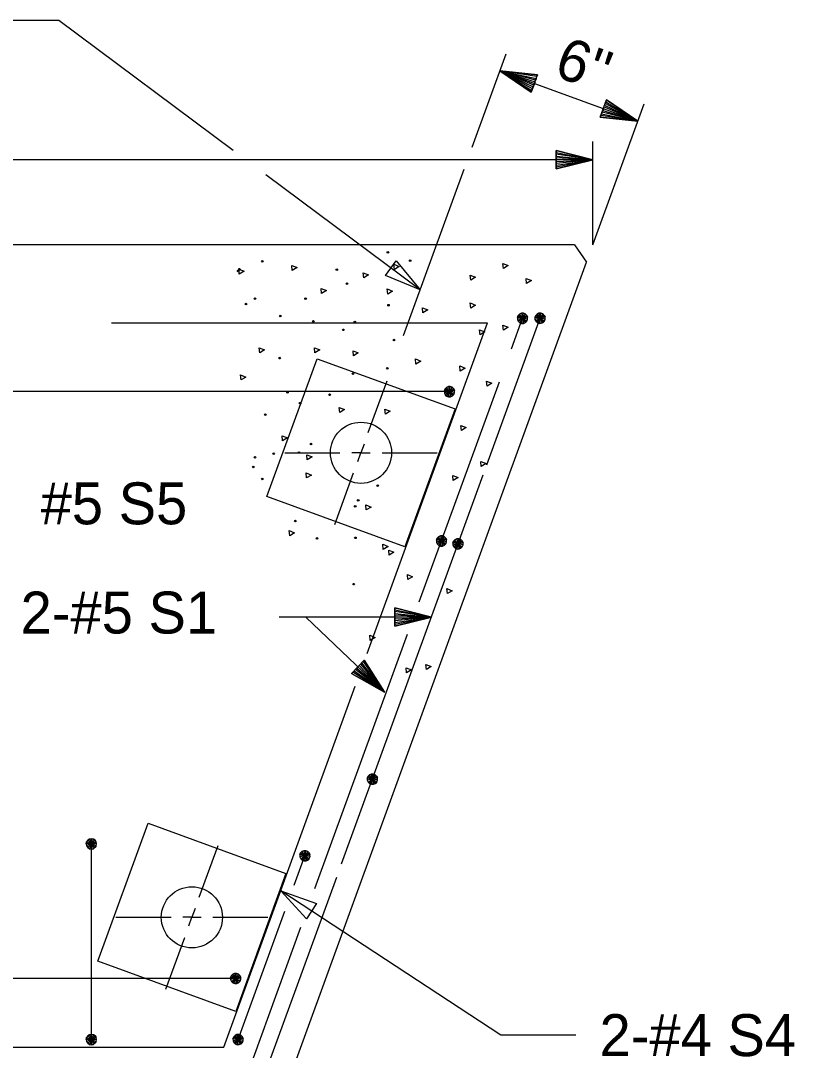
# Model space of a CAD drawing. Extents: x -408 to -23, y -15 to 117.
# Drawn here: x -73.415 to -70.778, y 60.38 to 63.89 of the extents above; entities that cross this region are included whole.
import ezdxf

# ---------------------------------------------------------------- set-up
doc = ezdxf.new("R2010")
doc.units = 0
for name, color, linetype in [('Arrowhead Terminators CELL', 7, 'Continuous'), ('Dimension Lines', 7, 'Continuous'), ('Rebar Lines', 7, 'Continuous'), ('Sup Concrete Girder Lines', 7, 'Continuous'), ('Sup Cored Slab Unit', 7, 'Continuous'), ('Text', 7, 'Continuous')]:
    doc.layers.add(name, color=color, linetype=linetype)

msp = doc.modelspace()

# ---------------------------------------------------------------- linework, layer by layer
at = {"layer": 'Arrowhead Terminators CELL'}
for points in [[(-72.0531, 62.9716), (-72.172, 63.0213), (-72.1347, 63.0714)], [(-72.5287, 60.9234), (-72.407, 60.881), (-72.4413, 60.8288)]]:
    msp.add_lwpolyline(points, close=True, dxfattribs=at)
at = {"layer": 'Dimension Lines'}
for p, q in [((-71.8758, 63.4587), (-71.7601, 63.7768)), ((-71.7814, 63.7181), (-71.3116, 63.5471)), ((-71.4651, 63.1251), (-71.2902, 63.6058)), ((-71.4651, 63.1251), (-71.4651, 63.4781)), ((-71.4651, 63.4156), (-75.257, 63.4156)), ((-72.1097, 62.8161), (-71.9032, 63.3835)), ((-72.2302, 62.4855), (-72.166, 62.6616)), ((-72.5142, 62.4168), (-72.3267, 62.4168)), ((-72.1835, 62.4169), (-71.996, 62.4168)), ((-72.3442, 62.172), (-72.2801, 62.3482)), ((-72.0153, 61.8567), (-72.4433, 61.8568)), ((-72.8062, 60.9023), (-72.742, 61.0785)), ((-73.0903, 60.8337), (-72.9027, 60.8337)), ((-72.7596, 60.8337), (-72.5721, 60.8337)), ((-72.9203, 60.5889), (-72.8561, 60.765))]:
    msp.add_line(p, q, dxfattribs=at)
for points in [[(-72.6909, 63.4471), (-73.285, 63.8898), (-73.8439, 63.8898)], [(-71.664, 63.6753), (-71.6661, 63.6694), (-71.7814, 63.7181), (-71.6683, 63.6636), (-71.6704, 63.6577), (-71.7814, 63.7181), (-71.6725, 63.6518), (-71.6747, 63.6459), (-71.7814, 63.7181), (-71.6533, 63.7047), (-71.6555, 63.6988), (-71.7814, 63.7181), (-71.6576, 63.693), (-71.6597, 63.6871), (-71.7814, 63.7181), (-71.6619, 63.6812), (-71.6747, 63.6459), (-71.6533, 63.7047), (-71.7814, 63.7181), (-71.6747, 63.6459)], [(-71.429, 63.5898), (-71.4311, 63.5839), (-71.3116, 63.5471), (-71.4333, 63.5781), (-71.4355, 63.5722), (-71.3116, 63.5471), (-71.4376, 63.5663), (-71.4397, 63.5605), (-71.3116, 63.5471), (-71.4183, 63.6192), (-71.4205, 63.6133), (-71.3116, 63.5471), (-71.4226, 63.6075), (-71.4248, 63.6015), (-71.3116, 63.5471), (-71.4269, 63.5957), (-71.4397, 63.5605), (-71.4183, 63.6192), (-71.3116, 63.5471), (-71.4397, 63.5605)], [(-71.5901, 63.4156), (-71.5901, 63.4094), (-71.4651, 63.4156), (-71.5901, 63.4031), (-71.5901, 63.3969), (-71.4651, 63.4156), (-71.5901, 63.3906), (-71.5901, 63.3844), (-71.4651, 63.4156), (-71.5901, 63.4469), (-71.5901, 63.4406), (-71.4651, 63.4156), (-71.5901, 63.4344), (-71.5901, 63.4281), (-71.4651, 63.4156), (-71.5901, 63.4219), (-71.5901, 63.3844), (-71.5901, 63.4469), (-71.4651, 63.4156), (-71.5901, 63.3844)], [(-72.0531, 62.9716), (-72.5796, 63.364)], [(-72.2443, 62.4462), (-72.2551, 62.4168), (-72.2235, 62.4167)], [(-72.2661, 62.3871), (-72.2554, 62.4166), (-72.2868, 62.4166)], [(-72.1403, 61.8567), (-72.1403, 61.8505), (-72.0153, 61.8567), (-72.1403, 61.8442), (-72.1403, 61.838), (-72.0153, 61.8567), (-72.1403, 61.8317), (-72.1403, 61.8255), (-72.0153, 61.8567), (-72.1403, 61.888), (-72.1403, 61.8817), (-72.0153, 61.8567), (-72.1403, 61.8755), (-72.1403, 61.8692), (-72.0153, 61.8567), (-72.1403, 61.863), (-72.1403, 61.8255), (-72.1403, 61.888), (-72.0153, 61.8567), (-72.1403, 61.8255)], [(-72.1749, 61.6013), (-72.4433, 61.8568), (-72.5342, 61.8568)], [(-72.2655, 61.6875), (-72.2697, 61.683), (-72.1749, 61.6013), (-72.274, 61.6784), (-72.2784, 61.6739), (-72.1749, 61.6013), (-72.2827, 61.6694), (-72.287, 61.6649), (-72.1749, 61.6013), (-72.2439, 61.7101), (-72.2482, 61.7056), (-72.1749, 61.6013), (-72.2525, 61.7011), (-72.2568, 61.6965), (-72.1749, 61.6013), (-72.2611, 61.692), (-72.287, 61.6649), (-72.2439, 61.7101), (-72.1749, 61.6013), (-72.287, 61.6649)], [(-71.5229, 60.4319), (-71.7788, 60.4319), (-72.5287, 60.9234)], [(-72.8203, 60.8631), (-72.8312, 60.8337), (-72.7996, 60.8336)], [(-72.8421, 60.804), (-72.8315, 60.8335), (-72.8629, 60.8335)]]:
    msp.add_lwpolyline(points, dxfattribs=at)
at = {"layer": 'Rebar Lines'}
for p, q in [((-71.8266, 62.3756), (-71.6448, 62.8751)), ((-71.7425, 62.7708), (-71.7045, 62.8751)), ((-73.1061, 62.8595), (-71.824, 62.8595)), ((-72.2343, 61.7322), (-71.824, 62.8595)), ((-72.0564, 61.9085), (-71.7834, 62.6584)), ((-71.9536, 62.6251), (-74.6002, 62.6251)), ((-72.0185, 61.8483), (-71.8389, 62.3417)), ((-72.3213, 61.0161), (-72.0184, 61.8483)), ((-72.412, 60.9313), (-72.0963, 61.7987)), ((-72.7226, 60.3908), (-72.2748, 61.6211)), ((-73.1742, 60.4168), (-73.1742, 61.0834)), ((-72.4825, 60.9434), (-72.4462, 61.0433)), ((-72.5622, 60.3543), (-72.338, 60.9704)), ((-72.6742, 60.4168), (-72.5147, 60.8549)), ((-72.622, 60.3543), (-72.46, 60.7994)), ((-72.6822, 60.6251), (-75.3697, 60.6251)), ((-74.0047, 60.3908), (-72.7226, 60.3908))]:
    msp.add_line(p, q, dxfattribs=at)
for points in [[(-71.6872, 62.8721), (-71.6873, 62.8789), (-71.69, 62.8852), (-71.695, 62.89), (-71.7015, 62.8925), (-71.7083, 62.8923), (-71.7146, 62.8896), (-71.7194, 62.8846), (-71.7219, 62.8782), (-71.7217, 62.8713), (-71.7189, 62.865), (-71.714, 62.8602), (-71.7076, 62.8577), (-71.7007, 62.8579), (-71.6945, 62.8607), (-71.6897, 62.8656), (-71.6872, 62.8721), (-71.7045, 62.8751), (-71.7219, 62.8782), (-71.7194, 62.8846), (-71.7045, 62.8751), (-71.7146, 62.8896), (-71.7083, 62.8923), (-71.7045, 62.8751), (-71.7015, 62.8925), (-71.695, 62.89), (-71.7045, 62.8751), (-71.69, 62.8852), (-71.6873, 62.8789), (-71.7045, 62.8751), (-71.6897, 62.8656), (-71.6945, 62.8607), (-71.7045, 62.8751), (-71.7007, 62.8579), (-71.7076, 62.8577), (-71.7045, 62.8751), (-71.714, 62.8602), (-71.7189, 62.865), (-71.7045, 62.8751), (-71.7217, 62.8713)], [(-71.6274, 62.8721), (-71.6275, 62.8789), (-71.6303, 62.8852), (-71.6353, 62.89), (-71.6417, 62.8925), (-71.6486, 62.8924), (-71.6549, 62.8896), (-71.6596, 62.8847), (-71.6621, 62.8782), (-71.662, 62.8714), (-71.6592, 62.8651), (-71.6543, 62.8603), (-71.6478, 62.8578), (-71.6409, 62.858), (-71.6347, 62.8607), (-71.6299, 62.8657), (-71.6274, 62.8721), (-71.6448, 62.8751), (-71.6621, 62.8782), (-71.6596, 62.8847), (-71.6448, 62.8751), (-71.6549, 62.8896), (-71.6486, 62.8924), (-71.6448, 62.8751), (-71.6417, 62.8925), (-71.6353, 62.89), (-71.6448, 62.8751), (-71.6303, 62.8852), (-71.6275, 62.8789), (-71.6448, 62.8751), (-71.6299, 62.8657), (-71.6347, 62.8607), (-71.6448, 62.8751), (-71.6409, 62.858), (-71.6478, 62.8578), (-71.6448, 62.8751), (-71.6543, 62.8603), (-71.6592, 62.8651), (-71.6448, 62.8751), (-71.662, 62.8714)], [(-71.9363, 62.6221), (-71.9364, 62.6289), (-71.9391, 62.6352), (-71.9441, 62.64), (-71.9506, 62.6425), (-71.9574, 62.6424), (-71.9637, 62.6396), (-71.9684, 62.6346), (-71.9709, 62.6282), (-71.9708, 62.6213), (-71.968, 62.615), (-71.9631, 62.6102), (-71.9566, 62.6077), (-71.9498, 62.6079), (-71.9435, 62.6107), (-71.9387, 62.6157), (-71.9363, 62.6221), (-71.9536, 62.6251), (-71.9709, 62.6282), (-71.9684, 62.6346), (-71.9536, 62.6251), (-71.9637, 62.6396), (-71.9574, 62.6424), (-71.9536, 62.6251), (-71.9506, 62.6425), (-71.9441, 62.64), (-71.9536, 62.6251), (-71.9391, 62.6352), (-71.9364, 62.6289), (-71.9536, 62.6251), (-71.9387, 62.6157), (-71.9435, 62.6107), (-71.9536, 62.6251), (-71.9498, 62.6079), (-71.9566, 62.6077), (-71.9536, 62.6251), (-71.9631, 62.6102), (-71.968, 62.615), (-71.9536, 62.6251), (-71.9708, 62.6213)], [(-71.9635, 62.113), (-71.9636, 62.1198), (-71.9663, 62.1261), (-71.9713, 62.1309), (-71.9777, 62.1334), (-71.9846, 62.1333), (-71.9909, 62.1305), (-71.9956, 62.1256), (-71.9982, 62.1191), (-71.998, 62.1123), (-71.9952, 62.106), (-71.9903, 62.1012), (-71.9839, 62.0987), (-71.977, 62.0988), (-71.9707, 62.1016), (-71.9659, 62.1065), (-71.9635, 62.113), (-71.9808, 62.1161), (-71.9982, 62.1191), (-71.9956, 62.1256), (-71.9808, 62.1161), (-71.9909, 62.1305), (-71.9846, 62.1333), (-71.9808, 62.1161), (-71.9777, 62.1334), (-71.9713, 62.1309), (-71.9808, 62.1161), (-71.9663, 62.1261), (-71.9636, 62.1198), (-71.9808, 62.1161), (-71.9659, 62.1065), (-71.9707, 62.1016), (-71.9808, 62.1161), (-71.977, 62.0988), (-71.9839, 62.0987), (-71.9808, 62.1161), (-71.9903, 62.1012), (-71.9952, 62.106), (-71.9808, 62.1161), (-71.998, 62.1123)], [(-71.9073, 62.1031), (-71.9074, 62.1099), (-71.9102, 62.1162), (-71.9151, 62.121), (-71.9216, 62.1235), (-71.9284, 62.1234), (-71.9347, 62.1206), (-71.9395, 62.1157), (-71.942, 62.1092), (-71.9418, 62.1024), (-71.939, 62.0961), (-71.9342, 62.0913), (-71.9277, 62.0888), (-71.9208, 62.0889), (-71.9146, 62.0917), (-71.9098, 62.0966), (-71.9073, 62.1031), (-71.9246, 62.1061), (-71.942, 62.1092), (-71.9395, 62.1157), (-71.9246, 62.1061), (-71.9347, 62.1206), (-71.9284, 62.1234), (-71.9246, 62.1061), (-71.9216, 62.1235), (-71.9151, 62.121), (-71.9246, 62.1061), (-71.9102, 62.1162), (-71.9074, 62.1099), (-71.9246, 62.1061), (-71.9098, 62.0966), (-71.9146, 62.0917), (-71.9246, 62.1061), (-71.9208, 62.0889), (-71.9277, 62.0888), (-71.9246, 62.1061), (-71.9342, 62.0913), (-71.939, 62.0961), (-71.9246, 62.1061), (-71.9418, 62.1024)], [(-72.199, 61.3015), (-72.1991, 61.3084), (-72.2019, 61.3147), (-72.2069, 61.3195), (-72.2133, 61.3219), (-72.2201, 61.3218), (-72.2264, 61.319), (-72.2312, 61.314), (-72.2337, 61.3076), (-72.2335, 61.3008), (-72.2308, 61.2945), (-72.2258, 61.2897), (-72.2194, 61.2872), (-72.2125, 61.2873), (-72.2062, 61.2901), (-72.2014, 61.2951), (-72.199, 61.3015), (-72.2163, 61.3046), (-72.2337, 61.3076), (-72.2312, 61.314), (-72.2163, 61.3046), (-72.2264, 61.319), (-72.2201, 61.3218), (-72.2163, 61.3046), (-72.2133, 61.3219), (-72.2069, 61.3195), (-72.2163, 61.3046), (-72.2019, 61.3147), (-72.1991, 61.3084), (-72.2163, 61.3046), (-72.2014, 61.2951), (-72.2062, 61.2901), (-72.2163, 61.3046), (-72.2125, 61.2873), (-72.2194, 61.2872), (-72.2163, 61.3046), (-72.2258, 61.2897), (-72.2308, 61.2945), (-72.2163, 61.3046), (-72.2335, 61.3008)], [(-73.1566, 61.0834), (-73.1579, 61.0901), (-73.1617, 61.0959), (-73.1674, 61.0997), (-73.1742, 61.101), (-73.1809, 61.0997), (-73.1867, 61.0959), (-73.1905, 61.0902), (-73.1918, 61.0834), (-73.1905, 61.0767), (-73.1867, 61.071), (-73.181, 61.0671), (-73.1742, 61.0658), (-73.1674, 61.0671), (-73.1618, 61.0709), (-73.1579, 61.0766), (-73.1566, 61.0834), (-73.1742, 61.0834), (-73.1918, 61.0834), (-73.1905, 61.0902), (-73.1742, 61.0834), (-73.1867, 61.0959), (-73.1809, 61.0997), (-73.1742, 61.0834), (-73.1742, 61.101), (-73.1674, 61.0997), (-73.1742, 61.0834), (-73.1617, 61.0959), (-73.1579, 61.0901), (-73.1742, 61.0834), (-73.1579, 61.0766), (-73.1618, 61.0709), (-73.1742, 61.0834), (-73.1674, 61.0671), (-73.1742, 61.0658), (-73.1742, 61.0834), (-73.181, 61.0671), (-73.1867, 61.071), (-73.1742, 61.0834), (-73.1905, 61.0767)], [(-72.4289, 61.0402), (-72.429, 61.047), (-72.4317, 61.0533), (-72.4367, 61.0581), (-72.4431, 61.0605), (-72.45, 61.0604), (-72.4563, 61.0576), (-72.461, 61.0527), (-72.4635, 61.0463), (-72.4634, 61.0394), (-72.4606, 61.0331), (-72.4557, 61.0283), (-72.4493, 61.0258), (-72.4423, 61.026), (-72.4361, 61.0288), (-72.4313, 61.0337), (-72.4289, 61.0402), (-72.4462, 61.0432), (-72.4635, 61.0463), (-72.461, 61.0527), (-72.4462, 61.0432), (-72.4563, 61.0576), (-72.45, 61.0604), (-72.4462, 61.0432), (-72.4431, 61.0605), (-72.4367, 61.0581), (-72.4462, 61.0432), (-72.4317, 61.0533), (-72.429, 61.047), (-72.4462, 61.0432), (-72.4313, 61.0337), (-72.4361, 61.0288), (-72.4462, 61.0432), (-72.4423, 61.026), (-72.4493, 61.0258), (-72.4462, 61.0432), (-72.4557, 61.0283), (-72.4606, 61.0331), (-72.4462, 61.0432), (-72.4634, 61.0394)], [(-72.6649, 60.6221), (-72.665, 60.6289), (-72.6678, 60.6352), (-72.6727, 60.64), (-72.6792, 60.6425), (-72.686, 60.6424), (-72.6923, 60.6396), (-72.697, 60.6346), (-72.6995, 60.6282), (-72.6994, 60.6213), (-72.6966, 60.615), (-72.6917, 60.6102), (-72.6853, 60.6077), (-72.6784, 60.6079), (-72.6721, 60.6107), (-72.6673, 60.6157), (-72.6649, 60.6221), (-72.6822, 60.6251), (-72.6995, 60.6282), (-72.697, 60.6346), (-72.6822, 60.6251), (-72.6923, 60.6396), (-72.686, 60.6424), (-72.6822, 60.6251), (-72.6792, 60.6425), (-72.6727, 60.64), (-72.6822, 60.6251), (-72.6678, 60.6352), (-72.665, 60.6289), (-72.6822, 60.6251), (-72.6673, 60.6157), (-72.6721, 60.6107), (-72.6822, 60.6251), (-72.6784, 60.6079), (-72.6853, 60.6077), (-72.6822, 60.6251), (-72.6917, 60.6102), (-72.6966, 60.615), (-72.6822, 60.6251), (-72.6994, 60.6213)], [(-73.1566, 60.4168), (-73.1579, 60.4235), (-73.1617, 60.4292), (-73.1674, 60.4331), (-73.1742, 60.4344), (-73.1809, 60.4331), (-73.1867, 60.4292), (-73.1905, 60.4235), (-73.1918, 60.4168), (-73.1905, 60.41), (-73.1867, 60.4043), (-73.181, 60.4005), (-73.1742, 60.3991), (-73.1674, 60.4005), (-73.1618, 60.4043), (-73.1579, 60.41), (-73.1566, 60.4168), (-73.1742, 60.4168), (-73.1918, 60.4168), (-73.1905, 60.4235), (-73.1742, 60.4168), (-73.1867, 60.4292), (-73.1809, 60.4331), (-73.1742, 60.4168), (-73.1742, 60.4344), (-73.1674, 60.4331), (-73.1742, 60.4168), (-73.1617, 60.4292), (-73.1579, 60.4235), (-73.1742, 60.4168), (-73.1579, 60.41), (-73.1618, 60.4043), (-73.1742, 60.4168), (-73.1674, 60.4005), (-73.1742, 60.3991), (-73.1742, 60.4168), (-73.181, 60.4005), (-73.1867, 60.4043), (-73.1742, 60.4168), (-73.1905, 60.41)], [(-72.6569, 60.4137), (-72.657, 60.4206), (-72.6597, 60.4269), (-72.6647, 60.4316), (-72.6711, 60.4341), (-72.678, 60.434), (-72.6843, 60.4312), (-72.689, 60.4262), (-72.6915, 60.4198), (-72.6913, 60.413), (-72.6886, 60.4066), (-72.6837, 60.4019), (-72.6773, 60.3994), (-72.6703, 60.3995), (-72.6641, 60.4023), (-72.6593, 60.4073), (-72.6569, 60.4137), (-72.6742, 60.4168), (-72.6915, 60.4198), (-72.689, 60.4262), (-72.6742, 60.4168), (-72.6843, 60.4312), (-72.678, 60.434), (-72.6742, 60.4168), (-72.6711, 60.4341), (-72.6647, 60.4316), (-72.6742, 60.4168), (-72.6597, 60.4269), (-72.657, 60.4206), (-72.6742, 60.4168), (-72.6593, 60.4073), (-72.6641, 60.4023), (-72.6742, 60.4168), (-72.6703, 60.3995), (-72.6773, 60.3994), (-72.6742, 60.4168), (-72.6837, 60.4019), (-72.6886, 60.4066), (-72.6742, 60.4168), (-72.6913, 60.413)]]:
    msp.add_lwpolyline(points, dxfattribs=at)
at = {"layer": 'Sup Concrete Girder Lines'}
for p, q in [((-71.5276, 63.1251), (-77.0833, 63.1251)), ((-71.5276, 63.1251), (-71.4864, 63.0664)), ((-72.557, 60.1251), (-71.4864, 63.0664))]:
    msp.add_line(p, q, dxfattribs=at)
for points in [[(-72.67, 63.0255), (-72.6715, 63.0427), (-72.6535, 63.0356), (-72.67, 63.0255)], [(-72.4897, 63.0378), (-72.4912, 63.055), (-72.4732, 63.0479), (-72.4897, 63.0378)], [(-72.1414, 63.0419), (-72.1428, 63.0591), (-72.1249, 63.052), (-72.1414, 63.0419)], [(-71.7699, 63.0451), (-71.7713, 63.0623), (-71.7534, 63.0552), (-71.7699, 63.0451)], [(-72.2459, 63.0132), (-72.2473, 63.0304), (-72.2294, 63.0233), (-72.2459, 63.0132)], [(-71.8811, 63.0053), (-71.8826, 63.0226), (-71.8646, 63.0155), (-71.8811, 63.0053)], [(-71.6904, 62.9935), (-71.6919, 63.0107), (-71.6739, 63.0036), (-71.6904, 62.9935)], [(-72.3893, 62.9599), (-72.3908, 62.9772), (-72.3728, 62.97), (-72.3893, 62.9599)], [(-72.1639, 62.9578), (-72.1654, 62.9751), (-72.1474, 62.968), (-72.1639, 62.9578)], [(-72.044, 62.8941), (-72.0455, 62.9113), (-72.0275, 62.9042), (-72.044, 62.8941)], [(-71.8811, 62.91), (-71.8826, 62.9273), (-71.8646, 62.9201), (-71.8811, 62.91)], [(-71.8494, 62.8186), (-71.8508, 62.8359), (-71.8328, 62.8287), (-71.8494, 62.8186)], [(-71.7699, 62.8345), (-71.7713, 62.8518), (-71.7534, 62.8446), (-71.7699, 62.8345)], [(-72.6003, 62.7571), (-72.6018, 62.7743), (-72.5838, 62.7672), (-72.6003, 62.7571)], [(-72.4119, 62.7571), (-72.4133, 62.7743), (-72.3953, 62.7672), (-72.4119, 62.7571)], [(-72.2807, 62.7468), (-72.2822, 62.764), (-72.2642, 62.7569), (-72.2807, 62.7468)], [(-72.0678, 62.7193), (-72.0693, 62.7365), (-72.0513, 62.7294), (-72.0678, 62.7193)], [(-71.9169, 62.6955), (-71.9184, 62.7127), (-71.9004, 62.7056), (-71.9169, 62.6955)], [(-72.6639, 62.6649), (-72.6653, 62.6821), (-72.6474, 62.675), (-72.6639, 62.6649)], [(-71.8255, 62.6438), (-71.827, 62.6611), (-71.809, 62.6539), (-71.8255, 62.6438)], [(-72.3278, 62.5542), (-72.3293, 62.5714), (-72.3113, 62.5643), (-72.3278, 62.5542)], [(-72.1721, 62.5481), (-72.1736, 62.5653), (-72.1556, 62.5582), (-72.1721, 62.5481)], [(-71.9129, 62.4928), (-71.9144, 62.5101), (-71.8964, 62.503), (-71.9129, 62.4928)], [(-72.5225, 62.4579), (-72.5239, 62.4751), (-72.506, 62.468), (-72.5225, 62.4579)], [(-72.4385, 62.3923), (-72.4399, 62.4096), (-72.422, 62.4024), (-72.4385, 62.3923)], [(-71.8453, 62.3697), (-71.8468, 62.3869), (-71.8288, 62.3798), (-71.8453, 62.3697)], [(-72.4406, 62.3309), (-72.442, 62.3481), (-72.424, 62.341), (-72.4406, 62.3309)], [(-71.9407, 62.322), (-71.9422, 62.3393), (-71.9242, 62.3321), (-71.9407, 62.322)], [(-72.2373, 62.2218), (-72.2387, 62.2391), (-72.2208, 62.2319), (-72.2373, 62.2218)], [(-72.4979, 62.1342), (-72.4994, 62.1514), (-72.4814, 62.1443), (-72.4979, 62.1342)], [(-72.1791, 62.0876), (-72.1806, 62.1048), (-72.1626, 62.0977), (-72.1791, 62.0876)], [(-72.1593, 62.0677), (-72.1607, 62.0849), (-72.1427, 62.0778), (-72.1593, 62.0677)], [(-72.0957, 61.9843), (-72.0971, 62.0015), (-72.0792, 61.9944), (-72.0957, 61.9843)], [(-71.9606, 61.9366), (-71.9621, 61.9538), (-71.9441, 61.9467), (-71.9606, 61.9366)], [(-72.2235, 61.7775), (-72.225, 61.7948), (-72.207, 61.7876), (-72.2235, 61.7775)], [(-72.0997, 61.6664), (-72.1011, 61.6837), (-72.0832, 61.6765), (-72.0997, 61.6664)], [(-72.0321, 61.6784), (-72.0336, 61.6956), (-72.0156, 61.6885), (-72.0321, 61.6784)]]:
    msp.add_lwpolyline(points, dxfattribs=at)
for centre, radius in [((-72.1634, 63.1), 0.00273), ((-72.0876, 63.0714), 0.00273), ((-72.6736, 63.0365), 0.00273), ((-72.6695, 63.0427), 0.00273), ((-72.5916, 63.0693), 0.00273), ((-72.3375, 63.0406), 0.00273), ((-72.3027, 62.9935), 0.00273), ((-72.6162, 62.9423), 0.00273), ((-72.4441, 62.9423), 0.00273), ((-72.647, 62.9238), 0.00273), ((-72.1613, 62.9197), 0.00273), ((-72.5301, 62.8828), 0.00273), ((-72.4174, 62.8644), 0.00273), ((-72.2761, 62.8624), 0.00273), ((-72.315, 62.8358), 0.00273), ((-72.1429, 62.8009), 0.00273), ((-72.5322, 62.7394), 0.00273), ((-72.2822, 62.6862), 0.00273), ((-72.1655, 62.7046), 0.00273), ((-72.5056, 62.6226), 0.00273), ((-72.4625, 62.5858), 0.00273), ((-72.3621, 62.6144), 0.00273), ((-72.5814, 62.5468), 0.00273), ((-72.2551, 62.4168), 0.1042), ((-72.4257, 62.4464), 0.00273), ((-72.5527, 62.4136), 0.00273), ((-72.4667, 62.4177), 0.00273), ((-72.6162, 62.4013), 0.00273), ((-72.6223, 62.3686), 0.00273), ((-72.5916, 62.3276), 0.00273), ((-72.1982, 62.305), 0.00273), ((-72.2748, 62.234), 0.00273), ((-72.2646, 62.2545), 0.00273), ((-72.4789, 62.1841), 0.00273), ((-72.4051, 62.1248), 0.00273), ((-72.274, 62.1268), 0.00273), ((-72.2802, 61.969), 0.00273), ((-72.8315, 60.8335), 0.1042)]:
    msp.add_circle(centre, radius, dxfattribs=at)
at = {"layer": 'Sup Cored Slab Unit'}
for points in [[(-72.4045, 62.7372), (-71.9346, 62.5662), (-72.1056, 62.0964), (-72.5755, 62.2674)], [(-72.9809, 61.1539), (-72.511, 60.9829), (-72.6821, 60.513), (-73.1519, 60.6841)]]:
    msp.add_lwpolyline(points, close=True, dxfattribs=at)

# ---------------------------------------------------------------- texts
at = {"layer": 'Text'}
msp.add_text("6''", height=0.14302, rotation=340.0105, dxfattribs=at).set_placement((-71.6028, 63.7033))
for s, p in [('#5 S5', (-73.3471, 62.1729)), ('2-#5 S1', (-73.4154, 61.8007)), ('2-#4 S4', (-71.442, 60.3604))]:
    msp.add_text(s, height=0.14302, dxfattribs=at).set_placement(p)

doc.saveas('drawing.dxf')
